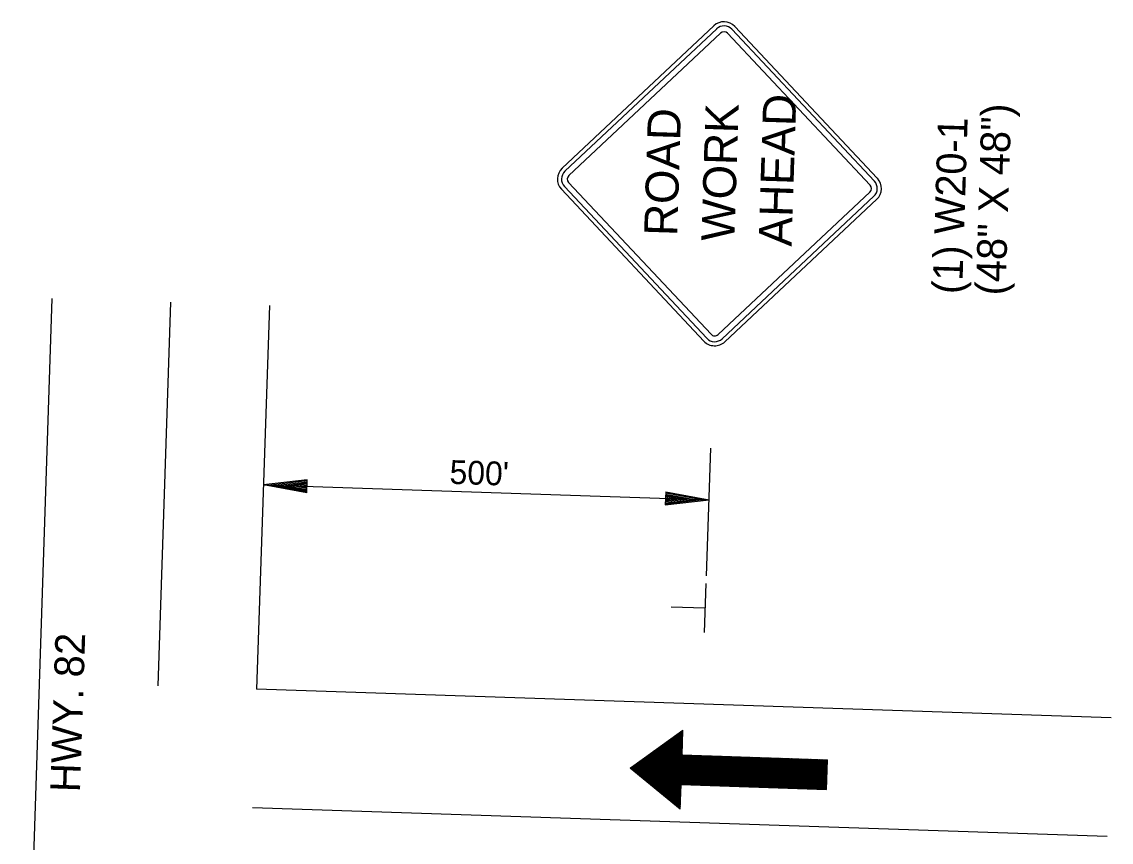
# Model space of a CAD drawing. Extents: x 977269 to 979191, y 1525946 to 1526973.
# Drawn here: x 978090.2 to 978310.1, y 1526179.9 to 1526345.4 of the extents above; entities that cross this region are included whole.
import ezdxf

# ---------------------------------------------------------------- set-up
doc = ezdxf.new("R2010")
doc.units = 0
for name, color, linetype in [('BDR_Plan Profile Grid 4', 7, 'Continuous'), ('R_Border', 7, 'Continuous'), ('STAMP', 7, 'Continuous'), ('STAMP_PP', 7, 'Continuous')]:
    doc.layers.add(name, color=color, linetype=linetype)

msp = doc.modelspace()

# ---------------------------------------------------------------- linework, layer by layer
at = {"layer": 'BDR_Plan Profile Grid 4'}
for p, q in [((978223.42, 1526202.29), (978214.29, 1526193.76)), ((978223.63, 1526202.35), (978214.37, 1526193.7)), ((978223.62, 1526202.21), (978214.45, 1526193.63)), ((978223.62, 1526202.07), (978214.53, 1526193.57)), ((978220.26, 1526200.02), (978213.91, 1526194.08)), ((978220.89, 1526200.48), (978213.98, 1526194.02)), ((978221.52, 1526200.93), (978214.06, 1526193.95)), ((978222.15, 1526201.39), (978214.14, 1526193.89)), ((978222.79, 1526201.84), (978214.22, 1526193.82)), ((978223.61, 1526201.93), (978214.61, 1526193.5)), ((978223.61, 1526201.79), (978214.68, 1526193.44)), ((978223.6, 1526201.65), (978214.76, 1526193.37)), ((978223.6, 1526201.5), (978214.84, 1526193.31)), ((978223.59, 1526201.36), (978214.92, 1526193.25)), ((978223.59, 1526201.22), (978214.99, 1526193.18)), ((978223.58, 1526201.08), (978215.07, 1526193.12)), ((978223.58, 1526200.94), (978215.15, 1526193.05)), ((978223.57, 1526200.8), (978215.23, 1526192.99)), ((978223.57, 1526200.66), (978215.31, 1526192.93)), ((978223.57, 1526200.51), (978215.38, 1526192.86)), ((978223.56, 1526200.37), (978215.46, 1526192.8)), ((978223.56, 1526200.23), (978215.54, 1526192.73)), ((978223.55, 1526200.09), (978215.62, 1526192.67)), ((978223.55, 1526199.95), (978215.69, 1526192.6)), ((978223.54, 1526199.81), (978215.77, 1526192.54)), ((978217.1, 1526197.75), (978213.52, 1526194.4)), ((978217.73, 1526198.21), (978213.59, 1526194.34)), ((978218.36, 1526198.66), (978213.67, 1526194.27)), ((978218.99, 1526199.11), (978213.75, 1526194.21)), ((978219.63, 1526199.57), (978213.83, 1526194.14)), ((978223.54, 1526199.67), (978215.85, 1526192.48)), ((978223.53, 1526199.53), (978215.93, 1526192.41)), ((978223.53, 1526199.38), (978216.01, 1526192.35)), ((978223.52, 1526199.24), (978216.08, 1526192.28)), ((978223.52, 1526199.1), (978216.16, 1526192.22)), ((978223.51, 1526198.96), (978216.24, 1526192.16)), ((978223.51, 1526198.82), (978216.32, 1526192.09)), ((978223.5, 1526198.68), (978216.39, 1526192.03)), ((978223.5, 1526198.54), (978216.47, 1526191.96)), ((978223.49, 1526198.39), (978216.55, 1526191.9)), ((978223.49, 1526198.25), (978216.63, 1526191.83)), ((978223.49, 1526198.11), (978216.71, 1526191.77)), ((978223.48, 1526197.97), (978216.78, 1526191.71)), ((978223.48, 1526197.83), (978216.86, 1526191.64)), ((978223.47, 1526197.69), (978216.94, 1526191.58)), ((978213.94, 1526195.48), (978213.13, 1526194.72)), ((978214.57, 1526195.93), (978213.21, 1526194.66)), ((978215.2, 1526196.39), (978213.28, 1526194.59)), ((978215.83, 1526196.84), (978213.36, 1526194.53)), ((978216.47, 1526197.3), (978213.44, 1526194.47)), ((978223.47, 1526197.55), (978217.02, 1526191.51)), ((978223.52, 1526197.46), (978217.09, 1526191.45)), ((978223.66, 1526197.46), (978217.17, 1526191.39)), ((978223.8, 1526197.45), (978217.25, 1526191.32)), ((978223.94, 1526197.45), (978217.33, 1526191.26)), ((978224.09, 1526197.44), (978217.41, 1526191.19)), ((978224.23, 1526197.44), (978217.48, 1526191.13)), ((978224.37, 1526197.43), (978217.56, 1526191.06)), ((978224.51, 1526197.43), (978217.64, 1526191)), ((978224.65, 1526197.42), (978217.72, 1526190.94)), ((978224.79, 1526197.42), (978217.79, 1526190.87)), ((978224.93, 1526197.41), (978217.87, 1526190.81)), ((978225.07, 1526197.41), (978217.95, 1526190.74)), ((978225.22, 1526197.4), (978218.03, 1526190.68)), ((978225.36, 1526197.4), (978218.11, 1526190.62)), ((978225.5, 1526197.39), (978218.18, 1526190.55)), ((978225.64, 1526197.39), (978218.26, 1526190.49)), ((978225.78, 1526197.38), (978218.34, 1526190.42)), ((978225.92, 1526197.38), (978218.42, 1526190.36)), ((978226.06, 1526197.38), (978218.49, 1526190.29)), ((978226.21, 1526197.37), (978218.57, 1526190.23)), ((978226.35, 1526197.37), (978218.65, 1526190.17)), ((978226.49, 1526197.36), (978218.73, 1526190.1)), ((978226.63, 1526197.36), (978218.81, 1526190.04)), ((978226.77, 1526197.35), (978218.88, 1526189.97)), ((978226.91, 1526197.35), (978218.96, 1526189.91)), ((978227.05, 1526197.34), (978219.04, 1526189.84)), ((978227.19, 1526197.34), (978219.12, 1526189.78)), ((978227.34, 1526197.33), (978219.19, 1526189.72)), ((978227.48, 1526197.33), (978219.27, 1526189.65)), ((978227.62, 1526197.32), (978219.35, 1526189.59)), ((978227.76, 1526197.32), (978219.43, 1526189.52)), ((978227.9, 1526197.31), (978219.51, 1526189.46)), ((978228.04, 1526197.31), (978219.58, 1526189.4)), ((978228.18, 1526197.3), (978219.66, 1526189.33)), ((978228.33, 1526197.3), (978219.74, 1526189.27)), ((978228.47, 1526197.29), (978219.82, 1526189.2)), ((978228.61, 1526197.29), (978219.89, 1526189.14)), ((978228.75, 1526197.29), (978219.97, 1526189.07)), ((978228.89, 1526197.28), (978220.05, 1526189.01)), ((978229.03, 1526197.28), (978220.13, 1526188.95)), ((978229.17, 1526197.27), (978220.21, 1526188.88)), ((978229.32, 1526197.27), (978220.28, 1526188.82)), ((978229.46, 1526197.26), (978223.28, 1526191.48)), ((978229.6, 1526197.26), (978223.42, 1526191.48)), ((978229.74, 1526197.25), (978223.56, 1526191.47)), ((978229.88, 1526197.25), (978223.7, 1526191.47)), ((978230.02, 1526197.24), (978223.84, 1526191.46)), ((978230.16, 1526197.24), (978223.98, 1526191.46)), ((978230.3, 1526197.23), (978224.12, 1526191.45)), ((978230.45, 1526197.23), (978224.27, 1526191.45)), ((978230.59, 1526197.22), (978224.41, 1526191.44)), ((978230.73, 1526197.22), (978224.55, 1526191.44)), ((978230.87, 1526197.21), (978224.69, 1526191.43)), ((978231.01, 1526197.21), (978224.83, 1526191.43)), ((978231.15, 1526197.21), (978224.97, 1526191.42)), ((978231.29, 1526197.2), (978225.11, 1526191.42)), ((978231.44, 1526197.2), (978225.25, 1526191.41)), ((978231.58, 1526197.19), (978225.4, 1526191.41)), ((978231.72, 1526197.19), (978225.54, 1526191.4)), ((978231.86, 1526197.18), (978225.68, 1526191.4)), ((978232, 1526197.18), (978225.82, 1526191.4)), ((978232.14, 1526197.17), (978225.96, 1526191.39)), ((978232.28, 1526197.17), (978226.1, 1526191.39)), ((978232.42, 1526197.16), (978226.24, 1526191.38)), ((978232.57, 1526197.16), (978226.39, 1526191.38)), ((978232.71, 1526197.15), (978226.53, 1526191.37)), ((978232.85, 1526197.15), (978226.67, 1526191.37)), ((978232.99, 1526197.14), (978226.81, 1526191.36)), ((978233.13, 1526197.14), (978226.95, 1526191.36)), ((978233.27, 1526197.13), (978227.09, 1526191.35)), ((978233.41, 1526197.13), (978227.23, 1526191.35)), ((978233.56, 1526197.13), (978227.37, 1526191.34)), ((978233.7, 1526197.12), (978227.52, 1526191.34)), ((978233.84, 1526197.12), (978227.66, 1526191.33)), ((978233.98, 1526197.11), (978227.8, 1526191.33)), ((978234.12, 1526197.11), (978227.94, 1526191.32)), ((978234.26, 1526197.1), (978228.08, 1526191.32)), ((978234.4, 1526197.1), (978228.22, 1526191.32)), ((978234.54, 1526197.09), (978228.36, 1526191.31)), ((978234.69, 1526197.09), (978228.51, 1526191.31)), ((978234.83, 1526197.08), (978228.65, 1526191.3)), ((978234.97, 1526197.08), (978228.79, 1526191.3)), ((978235.11, 1526197.07), (978228.93, 1526191.29)), ((978235.25, 1526197.07), (978229.07, 1526191.29)), ((978235.39, 1526197.06), (978229.21, 1526191.28)), ((978235.53, 1526197.06), (978229.35, 1526191.28)), ((978235.68, 1526197.05), (978229.49, 1526191.27)), ((978235.82, 1526197.05), (978229.64, 1526191.27)), ((978235.96, 1526197.05), (978229.78, 1526191.26)), ((978236.1, 1526197.04), (978229.92, 1526191.26)), ((978236.24, 1526197.04), (978230.06, 1526191.25)), ((978236.38, 1526197.03), (978230.2, 1526191.25)), ((978236.52, 1526197.03), (978230.34, 1526191.24)), ((978236.66, 1526197.02), (978230.48, 1526191.24)), ((978236.81, 1526197.02), (978230.63, 1526191.23)), ((978236.95, 1526197.01), (978230.77, 1526191.23)), ((978237.09, 1526197.01), (978230.91, 1526191.23)), ((978237.23, 1526197), (978231.05, 1526191.22)), ((978237.37, 1526197), (978231.19, 1526191.22)), ((978237.51, 1526196.99), (978231.33, 1526191.21)), ((978237.65, 1526196.99), (978231.47, 1526191.21)), ((978237.8, 1526196.98), (978231.61, 1526191.2)), ((978237.94, 1526196.98), (978231.76, 1526191.2)), ((978238.08, 1526196.97), (978231.9, 1526191.19)), ((978238.22, 1526196.97), (978232.04, 1526191.19)), ((978238.36, 1526196.96), (978232.18, 1526191.18)), ((978238.5, 1526196.96), (978232.32, 1526191.18)), ((978238.64, 1526196.96), (978232.46, 1526191.17)), ((978238.79, 1526196.95), (978232.6, 1526191.17)), ((978238.93, 1526196.95), (978232.75, 1526191.16)), ((978239.07, 1526196.94), (978232.89, 1526191.16)), ((978239.21, 1526196.94), (978233.03, 1526191.15)), ((978239.35, 1526196.93), (978233.17, 1526191.15)), ((978239.49, 1526196.93), (978233.31, 1526191.15)), ((978239.63, 1526196.92), (978233.45, 1526191.14)), ((978239.77, 1526196.92), (978233.59, 1526191.14)), ((978239.92, 1526196.91), (978233.74, 1526191.13)), ((978240.06, 1526196.91), (978233.88, 1526191.13)), ((978240.2, 1526196.9), (978234.02, 1526191.12)), ((978240.34, 1526196.9), (978234.16, 1526191.12)), ((978240.48, 1526196.89), (978234.3, 1526191.11)), ((978240.62, 1526196.89), (978234.44, 1526191.11)), ((978240.76, 1526196.88), (978234.58, 1526191.1)), ((978240.91, 1526196.88), (978234.72, 1526191.1)), ((978241.05, 1526196.88), (978234.87, 1526191.09)), ((978241.19, 1526196.87), (978235.01, 1526191.09)), ((978241.33, 1526196.87), (978235.15, 1526191.08)), ((978241.47, 1526196.86), (978235.29, 1526191.08)), ((978241.61, 1526196.86), (978235.43, 1526191.07)), ((978241.75, 1526196.85), (978235.57, 1526191.07)), ((978241.89, 1526196.85), (978235.71, 1526191.07)), ((978242.04, 1526196.84), (978235.86, 1526191.06)), ((978242.18, 1526196.84), (978236, 1526191.06)), ((978242.32, 1526196.83), (978236.14, 1526191.05)), ((978242.46, 1526196.83), (978236.28, 1526191.05)), ((978242.6, 1526196.82), (978236.42, 1526191.04)), ((978242.74, 1526196.82), (978236.56, 1526191.04)), ((978242.88, 1526196.81), (978236.7, 1526191.03)), ((978243.03, 1526196.81), (978236.84, 1526191.03)), ((978243.17, 1526196.8), (978236.99, 1526191.02)), ((978243.31, 1526196.8), (978237.13, 1526191.02)), ((978243.45, 1526196.8), (978237.27, 1526191.01)), ((978243.59, 1526196.79), (978237.41, 1526191.01)), ((978243.73, 1526196.79), (978237.55, 1526191)), ((978243.87, 1526196.78), (978237.69, 1526191)), ((978244.01, 1526196.78), (978237.83, 1526190.99)), ((978244.16, 1526196.77), (978237.98, 1526190.99)), ((978244.3, 1526196.77), (978238.12, 1526190.99)), ((978244.44, 1526196.76), (978238.26, 1526190.98)), ((978244.58, 1526196.76), (978238.4, 1526190.98)), ((978244.72, 1526196.75), (978238.54, 1526190.97)), ((978244.86, 1526196.75), (978238.68, 1526190.97)), ((978245, 1526196.74), (978238.82, 1526190.96)), ((978245.15, 1526196.74), (978238.96, 1526190.96)), ((978245.29, 1526196.73), (978239.11, 1526190.95)), ((978245.43, 1526196.73), (978239.25, 1526190.95)), ((978245.57, 1526196.72), (978239.39, 1526190.94)), ((978245.71, 1526196.72), (978239.53, 1526190.94)), ((978245.85, 1526196.72), (978239.67, 1526190.93)), ((978245.99, 1526196.71), (978239.81, 1526190.93)), ((978246.13, 1526196.71), (978239.95, 1526190.92)), ((978246.28, 1526196.7), (978240.1, 1526190.92)), ((978246.42, 1526196.7), (978240.24, 1526190.91)), ((978246.56, 1526196.69), (978240.38, 1526190.91)), ((978246.7, 1526196.69), (978240.52, 1526190.91)), ((978246.84, 1526196.68), (978240.66, 1526190.9)), ((978246.98, 1526196.68), (978240.8, 1526190.9)), ((978247.12, 1526196.67), (978240.94, 1526190.89)), ((978247.27, 1526196.67), (978241.08, 1526190.89)), ((978247.41, 1526196.66), (978241.23, 1526190.88)), ((978247.55, 1526196.66), (978241.37, 1526190.88)), ((978247.69, 1526196.65), (978241.51, 1526190.87)), ((978247.83, 1526196.65), (978241.65, 1526190.87)), ((978247.97, 1526196.64), (978241.79, 1526190.86)), ((978248.11, 1526196.64), (978241.93, 1526190.86)), ((978248.26, 1526196.64), (978242.07, 1526190.85)), ((978248.4, 1526196.63), (978242.22, 1526190.85)), ((978248.54, 1526196.63), (978242.36, 1526190.84)), ((978248.68, 1526196.62), (978242.5, 1526190.84)), ((978248.82, 1526196.62), (978242.64, 1526190.83)), ((978248.96, 1526196.61), (978242.78, 1526190.83)), ((978249.1, 1526196.61), (978242.92, 1526190.82)), ((978249.24, 1526196.6), (978243.06, 1526190.82)), ((978249.39, 1526196.6), (978243.21, 1526190.82)), ((978249.53, 1526196.59), (978243.35, 1526190.81)), ((978249.67, 1526196.59), (978243.49, 1526190.81)), ((978249.81, 1526196.58), (978243.63, 1526190.8)), ((978249.95, 1526196.58), (978243.77, 1526190.8)), ((978250.09, 1526196.57), (978243.91, 1526190.79)), ((978250.23, 1526196.57), (978244.05, 1526190.79)), ((978250.38, 1526196.56), (978244.19, 1526190.78)), ((978250.52, 1526196.56), (978244.34, 1526190.78)), ((978250.66, 1526196.55), (978244.48, 1526190.77)), ((978250.8, 1526196.55), (978244.62, 1526190.77)), ((978250.94, 1526196.55), (978244.76, 1526190.76)), ((978251.08, 1526196.54), (978244.9, 1526190.76)), ((978251.22, 1526196.54), (978245.04, 1526190.75)), ((978251.36, 1526196.53), (978245.18, 1526190.75)), ((978251.51, 1526196.53), (978245.33, 1526190.74)), ((978251.65, 1526196.52), (978245.47, 1526190.74)), ((978251.79, 1526196.52), (978245.61, 1526190.74)), ((978251.93, 1526196.51), (978245.75, 1526190.73)), ((978252.07, 1526196.51), (978245.89, 1526190.73)), ((978252.21, 1526196.5), (978246.03, 1526190.72)), ((978252.35, 1526196.5), (978246.17, 1526190.72)), ((978252.5, 1526196.49), (978246.31, 1526190.71)), ((978252.64, 1526196.49), (978246.46, 1526190.71)), ((978252.78, 1526196.48), (978246.6, 1526190.7)), ((978252.79, 1526196.36), (978246.74, 1526190.7)), ((978252.79, 1526196.22), (978246.88, 1526190.69)), ((978252.78, 1526196.08), (978247.02, 1526190.69)), ((978252.78, 1526195.93), (978247.16, 1526190.68)), ((978252.77, 1526195.79), (978247.3, 1526190.68)), ((978252.77, 1526195.65), (978247.45, 1526190.67)), ((978252.76, 1526195.51), (978247.59, 1526190.67)), ((978213.31, 1526195.03), (978213.05, 1526194.79)), ((978252.76, 1526195.37), (978247.73, 1526190.66)), ((978252.75, 1526195.23), (978247.87, 1526190.66)), ((978252.75, 1526195.09), (978248.01, 1526190.66)), ((978252.74, 1526194.95), (978248.15, 1526190.65)), ((978252.74, 1526194.8), (978248.29, 1526190.65)), ((978252.73, 1526194.66), (978248.43, 1526190.64)), ((978252.73, 1526194.52), (978248.58, 1526190.64)), ((978252.72, 1526194.38), (978248.72, 1526190.63)), ((978252.72, 1526194.24), (978248.86, 1526190.63)), ((978252.72, 1526194.1), (978249, 1526190.62)), ((978252.71, 1526193.96), (978249.14, 1526190.62)), ((978252.71, 1526193.81), (978249.28, 1526190.61)), ((978252.7, 1526193.67), (978249.42, 1526190.61)), ((978252.7, 1526193.53), (978249.57, 1526190.6)), ((978252.69, 1526193.39), (978249.71, 1526190.6)), ((978252.69, 1526193.25), (978249.85, 1526190.59)), ((978223.26, 1526191.47), (978220.36, 1526188.75)), ((978223.26, 1526191.33), (978220.44, 1526188.69)), ((978223.25, 1526191.19), (978220.52, 1526188.63)), ((978223.25, 1526191.04), (978220.59, 1526188.56)), ((978252.68, 1526193.11), (978249.99, 1526190.59)), ((978252.68, 1526192.97), (978250.13, 1526190.58)), ((978252.67, 1526192.83), (978250.27, 1526190.58)), ((978252.67, 1526192.68), (978250.41, 1526190.58)), ((978252.66, 1526192.54), (978250.55, 1526190.57)), ((978252.66, 1526192.4), (978250.7, 1526190.57)), ((978252.65, 1526192.26), (978250.84, 1526190.56)), ((978252.65, 1526192.12), (978250.98, 1526190.56)), ((978252.64, 1526191.98), (978251.12, 1526190.55)), ((978252.64, 1526191.84), (978251.26, 1526190.55)), ((978252.63, 1526191.69), (978251.4, 1526190.54)), ((978252.63, 1526191.55), (978251.54, 1526190.54)), ((978252.63, 1526191.41), (978251.69, 1526190.53)), ((978252.62, 1526191.27), (978251.83, 1526190.53)), ((978252.62, 1526191.13), (978251.97, 1526190.52)), ((978223.24, 1526190.9), (978220.67, 1526188.5)), ((978223.24, 1526190.76), (978220.75, 1526188.43)), ((978223.24, 1526190.62), (978220.83, 1526188.37)), ((978223.23, 1526190.48), (978220.91, 1526188.3)), ((978223.23, 1526190.34), (978220.98, 1526188.24)), ((978223.22, 1526190.2), (978221.06, 1526188.18)), ((978223.22, 1526190.06), (978221.14, 1526188.11)), ((978223.21, 1526189.91), (978221.22, 1526188.05)), ((978223.21, 1526189.77), (978221.29, 1526187.98)), ((978223.2, 1526189.63), (978221.37, 1526187.92)), ((978223.2, 1526189.49), (978221.45, 1526187.86)), ((978223.19, 1526189.35), (978221.53, 1526187.79)), ((978223.19, 1526189.21), (978221.61, 1526187.73)), ((978223.18, 1526189.07), (978221.68, 1526187.66)), ((978223.18, 1526188.92), (978221.76, 1526187.6)), ((978252.61, 1526190.99), (978252.11, 1526190.52)), ((978252.61, 1526190.85), (978252.25, 1526190.51)), ((978252.6, 1526190.71), (978252.39, 1526190.51)), ((978252.6, 1526190.56), (978252.53, 1526190.5)), ((978223.17, 1526188.78), (978221.84, 1526187.53)), ((978223.17, 1526188.64), (978221.92, 1526187.47)), ((978223.16, 1526188.5), (978221.99, 1526187.41)), ((978223.16, 1526188.36), (978222.07, 1526187.34)), ((978223.16, 1526188.22), (978222.15, 1526187.28)), ((978223.15, 1526188.08), (978222.23, 1526187.21)), ((978223.15, 1526187.94), (978222.31, 1526187.15)), ((978223.14, 1526187.79), (978222.38, 1526187.09)), ((978223.14, 1526187.65), (978222.46, 1526187.02)), ((978223.13, 1526187.51), (978222.54, 1526186.96)), ((978223.13, 1526187.37), (978222.62, 1526186.89)), ((978223.12, 1526187.23), (978222.69, 1526186.83)), ((978223.12, 1526187.09), (978222.77, 1526186.76)), ((978223.11, 1526186.95), (978222.85, 1526186.7)), ((978223.11, 1526186.8), (978222.93, 1526186.64)), ((978223.1, 1526186.66), (978223.01, 1526186.57)), ((978223.1, 1526186.52), (978223.08, 1526186.51))]:
    msp.add_line(p, q, dxfattribs=at)
at = {"layer": 'STAMP'}
for p, q in [((978096.33, 1526289.59), (978090.24, 1526107)), ((978120.26, 1526288.79), (978117.68, 1526211.38)), ((978140.19, 1526288.13), (978137.61, 1526210.71)), ((978228.41, 1526233.64), (978229.27, 1526259.38)), ((978147.83, 1526252.97), (978138.99, 1526251.94)), ((978147.82, 1526252.75), (978140.46, 1526251.89)), ((978147.74, 1526250.33), (978147.83, 1526252.97)), ((978138.99, 1526251.94), (978228.92, 1526248.94)), ((978147.74, 1526250.33), (978138.99, 1526251.94)), ((978147.75, 1526250.55), (978140.46, 1526251.89)), ((978147.81, 1526252.52), (978141.97, 1526251.84)), ((978147.75, 1526250.77), (978141.97, 1526251.84)), ((978147.81, 1526252.3), (978143.44, 1526251.79)), ((978147.76, 1526250.99), (978143.44, 1526251.79)), ((978147.8, 1526252.08), (978144.93, 1526251.74)), ((978147.77, 1526251.22), (978144.93, 1526251.74)), ((978147.79, 1526251.85), (978146.39, 1526251.69)), ((978147.78, 1526251.44), (978146.39, 1526251.69)), ((978220.17, 1526250.55), (978220.08, 1526247.92)), ((978220.17, 1526250.55), (978228.92, 1526248.94)), ((978220.08, 1526247.92), (978228.92, 1526248.94)), ((978220.09, 1526248.36), (978225.94, 1526249.04)), ((978220.09, 1526248.14), (978227.45, 1526248.99)), ((978220.1, 1526248.58), (978224.47, 1526249.09)), ((978220.11, 1526248.81), (978222.98, 1526249.14)), ((978220.12, 1526249.03), (978221.51, 1526249.19)), ((978220.13, 1526249.44), (978221.51, 1526249.19)), ((978220.14, 1526249.89), (978224.47, 1526249.09)), ((978220.14, 1526249.66), (978222.98, 1526249.14)), ((978220.15, 1526250.11), (978225.94, 1526249.04)), ((978220.16, 1526250.33), (978227.45, 1526248.99)), ((978228.02, 1526222.15), (978228.35, 1526232.04)), ((978228.04, 1526227.07), (978221.29, 1526227.3)), ((978310.05, 1526204.96), (978137.61, 1526210.71)), ((978213.01, 1526194.82), (978223.63, 1526202.45)), ((978223.46, 1526197.46), (978223.63, 1526202.45)), ((978223.46, 1526197.46), (978252.79, 1526196.48)), ((978252.6, 1526190.5), (978252.79, 1526196.48)), ((978223.1, 1526186.5), (978213.01, 1526194.82)), ((978223.1, 1526186.5), (978223.26, 1526191.48)), ((978223.26, 1526191.48), (978252.6, 1526190.5)), ((978309.25, 1526181.04), (978136.82, 1526186.79))]:
    msp.add_line(p, q, dxfattribs=at)
at = {"layer": 'STAMP_PP'}
for p, q in [((978199.26, 1526315.83), (978229.88, 1526344.58)), ((978199.83, 1526315.23), (978230.45, 1526343.97)), ((978200.62, 1526314.38), (978231.25, 1526343.12)), ((978232.66, 1526343.07), (978261.4, 1526312.45)), ((978233.51, 1526343.87), (978262.26, 1526313.25)), ((978234.12, 1526344.44), (978262.86, 1526313.82)), ((978228.47, 1526281.54), (978199.73, 1526312.16)), ((978229.32, 1526282.34), (978200.58, 1526312.96)), ((978227.86, 1526280.97), (978199.12, 1526311.59)), ((978261.36, 1526311.04), (978230.74, 1526282.29)), ((978262.16, 1526310.19), (978231.53, 1526281.44)), ((978262.73, 1526309.58), (978232.1, 1526280.84))]:
    msp.add_line(p, q, dxfattribs=at)
for centre, radius, start, end in [((978231.93, 1526342.39), 3, 43.1838, 133.1838), ((978231.93, 1526342.39), 2.17, 43.1838, 133.1838), ((978231.93, 1526342.39), 1, 43.1838, 133.1838), ((978201.31, 1526313.65), 3, 133.1838, 223.1838), ((978201.31, 1526313.65), 2.17, 133.1838, 223.1838), ((978201.31, 1526313.65), 1, 133.1838, 223.1838), ((978260.68, 1526311.76), 1, 313.1838, 43.1838), ((978260.68, 1526311.76), 2.17, 313.1838, 43.1838), ((978260.68, 1526311.76), 3, 313.1838, 43.1838), ((978230.05, 1526283.02), 2.17, 223.1838, 313.1838), ((978230.05, 1526283.02), 1, 223.1838, 313.1838), ((978230.05, 1526283.02), 3, 223.1838, 313.1838)]:
    msp.add_arc(centre, radius, start, end, dxfattribs=at)

# ---------------------------------------------------------------- texts
at = {"layer": 'R_Border'}
for s, height, rotation, p in [('(48" X 48")', 6, 88.1838, (978288.7, 1526290.13)), ('(1) W20-1', 6, 88.1838, (978279.97, 1526290.4)), ("500'", 4.8, 358.0901, (978176.5, 1526252.18)), ('HWY. 82', 6, 88.0901, (978101.98, 1526189.89))]:
    msp.add_text(s, height=height, rotation=rotation, dxfattribs=at).set_placement(p)
at = {"layer": 'STAMP_PP'}
for s, p in [(' AHEAD ', (978245.48, 1526297.54)), (' ROAD ', (978222.38, 1526299.62)), ('WORK', (978234.01, 1526301.06))]:
    msp.add_text(s, height=6.667, rotation=88.1838, dxfattribs=at).set_placement(p)

doc.saveas('drawing.dxf')
